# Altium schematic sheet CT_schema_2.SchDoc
size 278 x 262 mm
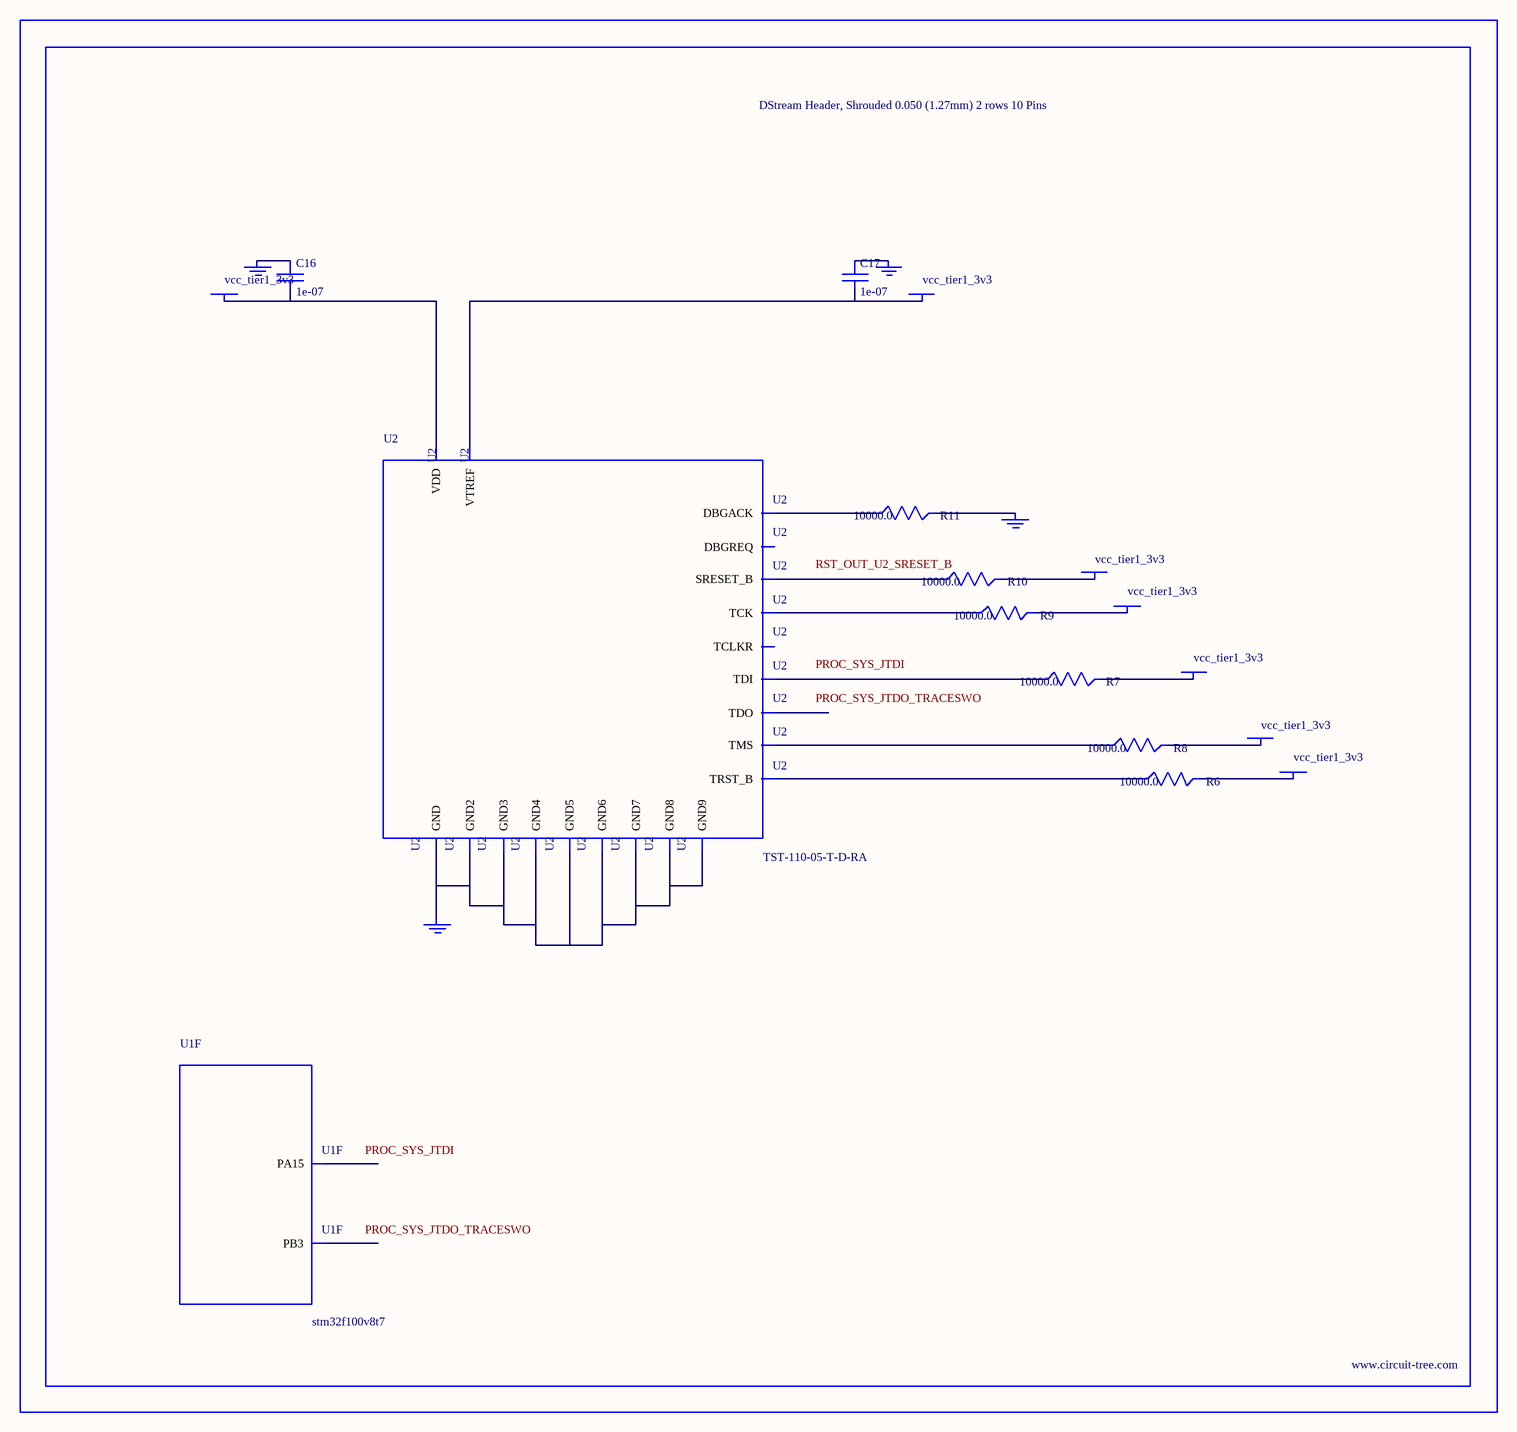
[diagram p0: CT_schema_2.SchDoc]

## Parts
BORDER1  (no value)
C16  1e-07  [C0402]
C17  1e-07  [C0402]
GND_INSTANCE_1_0  (no value)
GND_INSTANCE_1_1  (no value)
GND_INSTANCE_1_2  (no value)
GND_INSTANCE_1_3  (no value)
POWER_INSTANCE_1_0  vcc_tier1_3v3
POWER_INSTANCE_1_1  vcc_tier1_3v3
POWER_INSTANCE_1_2  vcc_tier1_3v3
POWER_INSTANCE_1_3  vcc_tier1_3v3
POWER_INSTANCE_1_4  vcc_tier1_3v3
POWER_INSTANCE_1_5  vcc_tier1_3v3
POWER_INSTANCE_1_6  vcc_tier1_3v3
R6  10000.0  [R0603]
R7  10000.0  [R0603]
R8  10000.0  [R0603]
R9  10000.0  [R0603]
R10  10000.0  [R0603]
R11  10000.0  [R0603]
U1  stm32f100v8t7  [LQFP100]  (part F of 7)
U2  TST-110-05-T-D-RA  [TST-110-05-T-D-RA]

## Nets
NetC16_1: C16.1 GND_INSTANCE_1_1.0(GND)
NetC16_2: C16.2 POWER_INSTANCE_1_1.0(PWR) U2.2(VDD)
NetC17_1: C17.1 GND_INSTANCE_1_0.0(GND)
NetC17_2: C17.2 POWER_INSTANCE_1_0.0(PWR) U2.1(VTREF)
NetGND_INSTANCE_1_2_0: GND_INSTANCE_1_2.0(GND) R11.2
NetGND_INSTANCE_1_3_0: GND_INSTANCE_1_3.0(GND) U2.4(GND) U2.6(GND2) U2.8(GND3) U2.10(GND4) U2.12(GND5) U2.14(GND6) U2.16(GND7) U2.18(GND8) U2.20(GND9)
NetPOWER_INSTANCE_1_2_0: POWER_INSTANCE_1_2.0(PWR) R6.2
NetPOWER_INSTANCE_1_3_0: POWER_INSTANCE_1_3.0(PWR) R7.2
NetPOWER_INSTANCE_1_4_0: POWER_INSTANCE_1_4.0(PWR) R8.2
NetPOWER_INSTANCE_1_5_0: POWER_INSTANCE_1_5.0(PWR) R9.2
NetPOWER_INSTANCE_1_6_0: POWER_INSTANCE_1_6.0(PWR) R10.2
NetR6_1: R6.1 U2.3(TRST_B)
NetR7_1: R7.1 U2.5(TDI)
NetR8_1: R8.1 U2.7(TMS)
NetR9_1: R9.1 U2.9(TCK)
NetR10_1: R10.1 U2.15(SRESET_B)
NetR11_1: R11.1 U2.19(DBGACK)

Not connected (* = marked no-connect by the designer): U1 77(PA15) 89(PB3); U2 11(TCLKR) 13(TDO) 17(DBGREQ)

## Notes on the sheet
- Labels drawn without touching a wire or pin: PROC_SYS_JTDI, PROC_SYS_JTDO_TRACESWO, RST_OUT_U2_SRESET_B

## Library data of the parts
BORDER1 = BORDER_PAGE1
C16 C17 = C0402C104K3RACTU
GND_INSTANCE_1_0-GND_INSTANCE_1_3 = GND
POWER_INSTANCE_1_0-POWER_INSTANCE_1_6 = PWR
R6-R11 = RC0603JR-0710KL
